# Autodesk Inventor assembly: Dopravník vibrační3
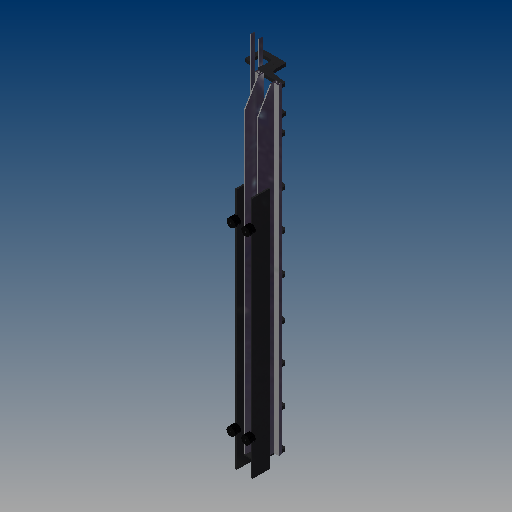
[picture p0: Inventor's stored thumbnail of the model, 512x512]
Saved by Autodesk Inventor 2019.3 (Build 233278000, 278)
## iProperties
Created: 2019-03
Part Number: Dopravník vibrační3
Material: Všeobecné
Document SubType Name: Assembly
Designer: B-hon
Mass: 40957.2 g
Surface Area: 30516.4 cm^2
Volume: 7408.73 cm^3
Density: 5.52823 g/cm^3
Author: B-hon
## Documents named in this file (13)
- C:\Users\B-hon\OneDrive\Plocha\Bakalářka22\Vibrační dopravník3\Dopravník vibrační3.iam
- C:\Users\B-hon\OneDrive\Plocha\Bakalářka22\Vibrační pohon2\Vibrační pohon SLL800-1200.iam
- C:\Users\B-hon\OneDrive\Plocha\Bakalářka22\Vibrační dopravník3\Spodní lišta.ipt
- C:\Users\B-hon\OneDrive\Plocha\Bakalářka22\Vibrační dopravník3\Lišta1.ipt
- C:\Users\B-hon\OneDrive\Plocha\Bakalářka22\Vibrační dopravník3\Lišta2.ipt
- C:\Users\B-hon\OneDrive\Plocha\Bakalářka22\Vibrační dopravník3\Spodní lišta2.ipt
- C:\Users\B-hon\OneDrive\Plocha\Bakalářka22\Vibrační dopravník3\Lišta vodící.ipt
- C:\Users\B-hon\OneDrive\Plocha\Bakalářka22\Vibrační dopravník3\Lišta vodící2.ipt
- C:\Users\B-hon\OneDrive\Plocha\Bakalářka22\Vibrační dopravník3\Třmen.ipt
- C:\Users\B-hon\OneDrive\Plocha\Bakalářka22\Držák dráhy2.ipt
- C:\Users\B-hon\OneDrive\Plocha\Bakalářka22\Držák dráhy3.ipt
- C:\Users\B-hon\OneDrive\Plocha\Bakalářka22\Držák dráhy4.ipt
- C:\Users\B-hon\OneDrive\Plocha\Bakalářka22\Vibrační dopravník3\Plech krycí.ipt
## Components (19 placed, 12 different names)
1. Vibrační pohon SLL800-1200:1 [sub-assembly] — Proti sobě:32, Proti sobě:33, Stejný směr:20, Proti sobě:41, Proti sobě:49, Stejný směr:39
2. Lišta1:1 — Proti sobě:9, Proti sobě:12, Stejný směr:16, Stejný směr:17, Stejný směr:30, Proti sobě:46, Stejný směr:35, Stejný směr:36
3. Lišta2:1 — Stejný směr:18, Proti sobě:42, Stejný směr:26, Stejný směr:31, Proti sobě:45
4. Spodní lišta:1 — Proti sobě:9, Proti sobě:13, Stejný směr:17, Stejný směr:18, Proti sobě:34, Stejný směr:19, Stejný směr:29, Stejný směr:30, Stejný směr:31
5. Spodní lišta2:1 — Proti sobě:12, Proti sobě:13, Proti sobě:17, Stejný směr:19, Proti sobě:47
6. Lišta vodící:1 — Proti sobě:17, Stejný směr:37, Stejný směr:38
7. Plech krycí:1 — Proti sobě:46, Stejný směr:35, Stejný směr:36
8. Lišta vodící2:1 — Proti sobě:47, Stejný směr:37, Stejný směr:38
9. Držák dráhy2:1 — Proti sobě:32, Proti sobě:33, Stejný směr:16, Proti sobě:34, Stejný směr:20, Stejný směr:29
10. Držák dráhy2:2
11. Držák dráhy2:3
12. Držák dráhy2:4 — Proti sobě:45
13. Držák dráhy4:1 — Proti sobě:41, Proti sobě:42, Stejný směr:26, Stejný směr:40
14. Držák dráhy4:2
15. Držák dráhy4:3
16. Třmen:1 — Vložit:1, Proti sobě:48
17. Držák dráhy3:1 — Vložit:1, Proti sobě:48, Proti sobě:49, Stejný směr:39, Stejný směr:40
18. Třmen:2
19. Držák dráhy3:2
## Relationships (30: Flush 15, Mate 14, Insert 1)
- Proti sobě:9 [Mate]: Lišta1:1 ↔ Spodní lišta:1
- Proti sobě:12 [Mate]: Lišta1:1 ↔ Spodní lišta2:1
- Proti sobě:13 [Mate]: Spodní lišta:1 ↔ Spodní lišta2:1
- Proti sobě:17 [Mate]: Spodní lišta2:1 ↔ Lišta vodící:1
- Proti sobě:32 [Mate]: Vibrační pohon SLL800-1200:1 ↔ Držák dráhy2:1
- Proti sobě:33 [Mate]: Vibrační pohon SLL800-1200:1 ↔ Držák dráhy2:1
- Stejný směr:16 [Flush]: Lišta1:1 ↔ Držák dráhy2:1
- Stejný směr:17 [Flush]: Lišta1:1 ↔ Spodní lišta:1
- Stejný směr:18 [Flush]: Lišta2:1 ↔ Spodní lišta:1
- Proti sobě:34 [Mate]: Spodní lišta:1 ↔ Držák dráhy2:1
- Stejný směr:19 [Flush]: Spodní lišta:1 ↔ Spodní lišta2:1
- Stejný směr:20 [Flush]: Vibrační pohon SLL800-1200:1 ↔ Držák dráhy2:1
- Proti sobě:41 [Mate]: Vibrační pohon SLL800-1200:1 ↔ Držák dráhy4:1
- Proti sobě:42 [Mate]: Lišta2:1 ↔ Držák dráhy4:1
- Stejný směr:26 [Flush]: Lišta2:1 ↔ Držák dráhy4:1
- Stejný směr:29 [Flush]: Spodní lišta:1 ↔ Držák dráhy2:1
- Stejný směr:30 [Flush]: Lišta1:1 ↔ Spodní lišta:1
- Stejný směr:31 [Flush]: Lišta2:1 ↔ Spodní lišta:1
- Proti sobě:45 [Mate]: Lišta2:1 ↔ Držák dráhy2:4
- Proti sobě:46 [Mate]: Lišta1:1 ↔ Plech krycí:1
- Stejný směr:35 [Flush]: Lišta1:1 ↔ Plech krycí:1
- Stejný směr:36 [Flush]: Lišta1:1 ↔ Plech krycí:1
- Proti sobě:47 [Mate]: Spodní lišta2:1 ↔ Lišta vodící2:1
- Stejný směr:37 [Flush]: Lišta vodící:1 ↔ Lišta vodící2:1
- Stejný směr:38 [Flush]: Lišta vodící:1 ↔ Lišta vodící2:1
- Vložit:1 [Insert]: Třmen:1 ↔ Držák dráhy3:1
- Proti sobě:48 [Mate]: Třmen:1 ↔ Držák dráhy3:1
- Proti sobě:49 [Mate]: Vibrační pohon SLL800-1200:1 ↔ Držák dráhy3:1
- Stejný směr:39 [Flush]: Vibrační pohon SLL800-1200:1 ↔ Držák dráhy3:1
- Stejný směr:40 [Flush]: Držák dráhy4:1 ↔ Držák dráhy3:1
